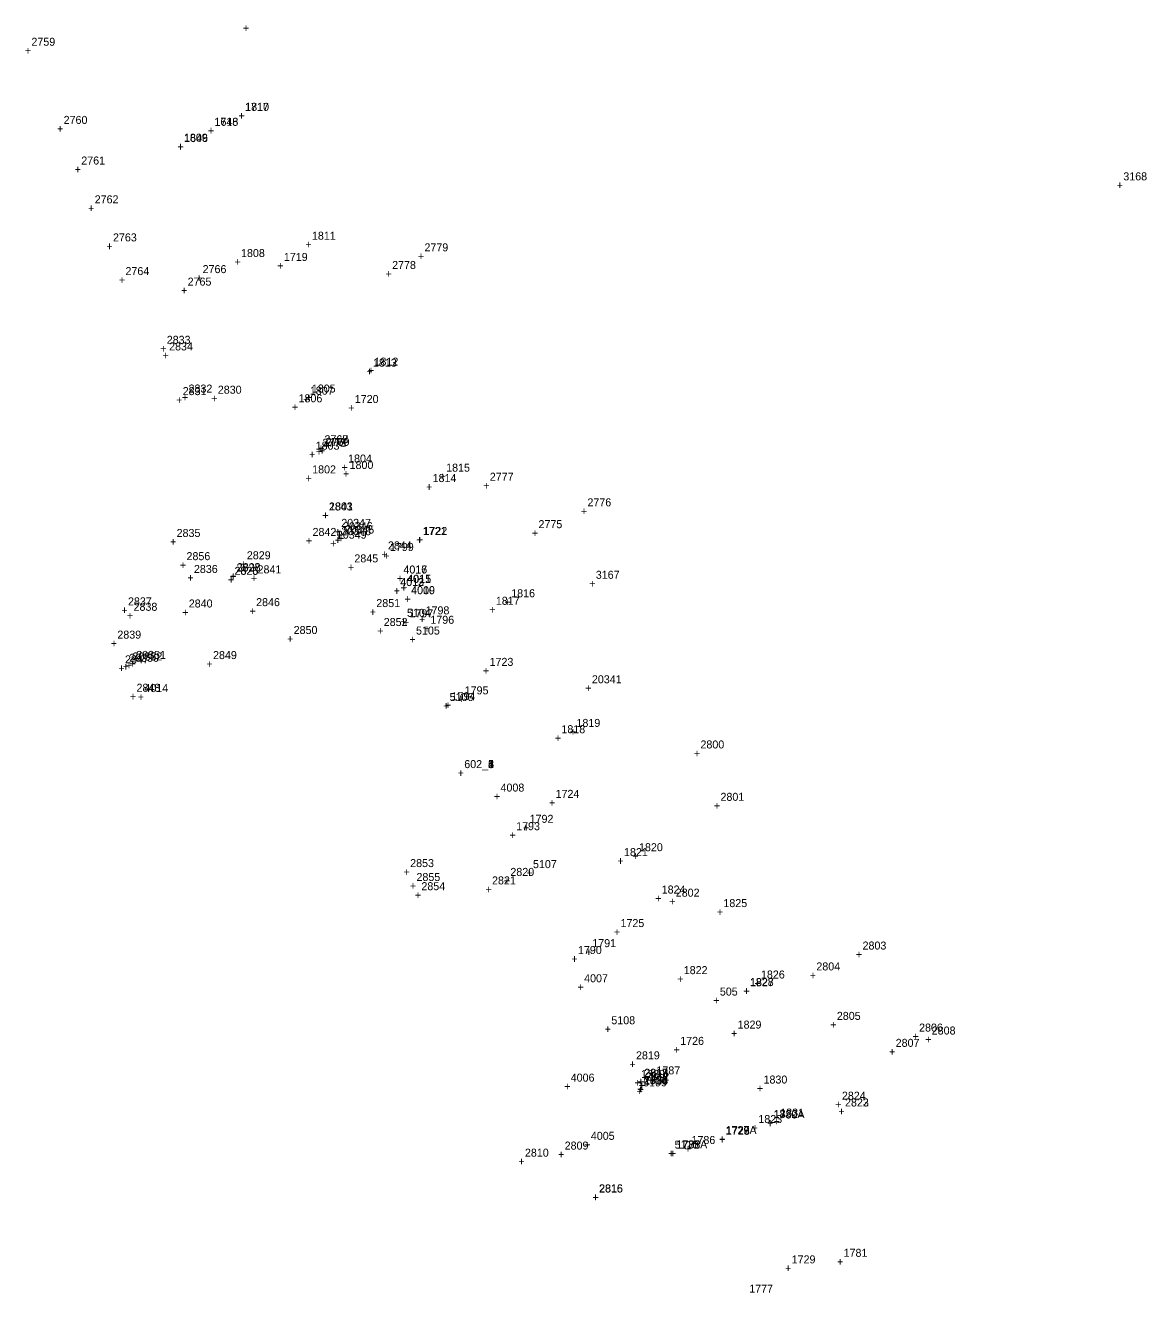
# Model space of a CAD drawing. Extents: x 1036751 to 1042192, y 772604 to 785439.
# Drawn here: x 1039702.1 to 1040052.6, y 775804.7 to 776200.7 of the extents above; entities that cross this region are included whole.
import ezdxf

# ---------------------------------------------------------------- set-up
doc = ezdxf.new("R2010")
doc.units = 0
for name, color, linetype in [('S_Bridge_Centerline', 7, 'Continuous'), ('S_Bridge_Deck', 7, 'Continuous'), ('S_Buildings', 7, 'Continuous'), ('S_Buildings_Attachments', 7, 'Continuous'), ('S_Buildings_SillElevation', 7, 'Continuous'), ('S_Control_Geodetic_ControlPoint', 7, 'Continuous'), ('S_Control_Temp_Traverse', 7, 'Continuous'), ('S_Control_Traverse_Point', 7, 'Continuous'), ('S_Curb_Type_3', 7, 'Continuous'), ('S_Drainage_CB', 7, 'Continuous'), ('S_Drainage_Culvert_Top', 7, 'Continuous'), ('S_Drainage_Invert', 7, 'Continuous'), ('S_Drainage_Sump', 7, 'Continuous'), ('S_Fencing_PostAndRail', 7, 'Continuous'), ('S_Ground_LevelString', 7, 'Continuous'), ('S_Property_IronPipeFound', 7, 'Continuous'), ('S_Property_Mailbox', 7, 'Continuous'), ('S_Roadway_Centerline', 7, 'Continuous'), ('S_Roadway_Edge_Pavement', 7, 'Continuous'), ('S_Roadway_Edge_TW', 7, 'Continuous'), ('S_Traffic_Sign_DoublePost', 7, 'Continuous'), ('S_Traffic_Sign_SinglePost', 7, 'Continuous'), ('S_Trees_Conifer_Pay', 7, 'Continuous'), ('S_Trees_Decid_Pay', 7, 'Continuous'), ('S_Utilities_GuyWire3', 7, 'Continuous'), ('S_Utilities_Pole_Power', 7, 'Continuous'), ('S_Utilities_UG_Sanitary_MH', 7, 'Continuous'), ('S_Utilities_UG_Sanitary_Sewer', 7, 'Continuous'), ('S_Utilities_UG_Water_Gate', 7, 'Continuous'), ('S_Utilities_UG_Water_Line', 7, 'Continuous')]:
    doc.layers.add(name, color=color, linetype=linetype)

msp = doc.modelspace()

# ---------------------------------------------------------------- texts
at = {"layer": 'S_Bridge_Centerline'}
for s, p in [('1728', (1039921.11, 775854.05)), ('+', (1039919.04, 775851.3)), ('+', (1039939.61, 775811.12)), ('1729', (1039941.67, 775813.87))]:
    msp.add_text(s, height=2.5, dxfattribs=at).set_placement(p)
at = {"layer": 'S_Bridge_Deck'}
for s, p in [('1780', (1039936.03, 775859.15)), ('1779', (1039921.04, 775854.1)), ('+', (1039933.97, 775856.4)), ('1778', (1039905.68, 775849.72)), ('+', (1039918.98, 775851.35)), ('+', (1039903.61, 775846.97)), ('1781', (1039957.9, 775815.92)), ('+', (1039955.84, 775813.17)), ('1777', (1039928.4, 775804.72))]:
    msp.add_text(s, height=2.5, dxfattribs=at).set_placement(p)
at = {"layer": 'S_Buildings'}
for s, p in [('2835', (1039749.43, 776040.85)), ('+', (1039747.37, 776038.1)), ('2836', (1039754.84, 776029.6)), ('+', (1039752.78, 776026.85)), ('+', (1039732.17, 776016.72)), ('2837', (1039734.23, 776019.47)), ('2853', (1039822.43, 775937.7)), ('+', (1039820.37, 775934.95)), ('2854', (1039825.94, 775930.48)), ('+', (1039823.88, 775927.73))]:
    msp.add_text(s, height=2.5, dxfattribs=at).set_placement(p)
at = {"layer": 'S_Buildings_Attachments'}
for s, p in [('2833', (1039746.35, 776101.2)), ('+', (1039744.29, 776098.45)), ('2831', (1039751.33, 776085.17)), ('2832', (1039753.16, 776085.97)), ('+', (1039749.27, 776082.42)), ('+', (1039751.1, 776083.22))]:
    msp.add_text(s, height=2.5, dxfattribs=at).set_placement(p)
at = {"layer": 'S_Buildings_SillElevation'}
for s, p in [('2834', (1039747.08, 776099.13)), ('+', (1039745.02, 776096.38)), ('2856', (1039752.52, 776033.6)), ('+', (1039750.46, 776030.85)), ('2855', (1039824.4, 775933.34)), ('+', (1039822.34, 775930.59))]:
    msp.add_text(s, height=2.5, dxfattribs=at).set_placement(p)
at = {"layer": 'S_Control_Geodetic_ControlPoint'}
msp.add_text('+', height=2.5, dxfattribs=at).set_placement((1039770.13, 776198.61))
msp.add_text('+', height=2.5, dxfattribs=at).set_placement((1039770.13, 776198.61))
msp.add_text('+', height=2.5, dxfattribs=at).set_placement((1039770.13, 776198.61))
msp.add_text('+', height=2.5, dxfattribs=at).set_placement((1039770.13, 776198.61))
msp.add_text('+', height=2.5, dxfattribs=at).set_placement((1039770.13, 776198.61))
msp.add_text('+', height=2.5, dxfattribs=at).set_placement((1039770.13, 776198.61))
at = {"layer": 'S_Control_Temp_Traverse'}
for s, p in [('602', (1039839.34, 775968.62)), ('602', (1039839.34, 775968.62)), ('602', (1039839.34, 775968.62)), ('602', (1039839.34, 775968.62)), ('602', (1039839.34, 775968.62)), ('602', (1039839.34, 775968.62)), ('602_6', (1039839.34, 775968.62)), ('602_4', (1039839.34, 775968.62)), ('602_5', (1039839.34, 775968.62)), ('602_2', (1039839.34, 775968.62)), ('602_3', (1039839.34, 775968.62)), ('602_1', (1039839.34, 775968.62)), ('+', (1039837.28, 775965.87)), ('+', (1039837.28, 775965.87)), ('+', (1039837.28, 775965.87)), ('+', (1039837.28, 775965.87)), ('+', (1039837.28, 775965.87)), ('+', (1039837.28, 775965.87)), ('+', (1039837.28, 775965.87)), ('+', (1039837.28, 775965.87)), ('+', (1039837.28, 775965.87)), ('+', (1039837.28, 775965.87)), ('+', (1039837.28, 775965.87)), ('+', (1039837.28, 775965.87))]:
    msp.add_text(s, height=2.5, dxfattribs=at).set_placement(p)
at = {"layer": 'S_Control_Traverse_Point'}
for s, p in [('505', (1039919.22, 775897.55)), ('505', (1039919.22, 775897.55)), ('505', (1039919.22, 775897.55)), ('505', (1039919.22, 775897.55)), ('505', (1039919.22, 775897.55)), ('505', (1039919.22, 775897.55)), ('+', (1039917.16, 775894.8)), ('+', (1039917.16, 775894.8)), ('+', (1039917.16, 775894.8)), ('+', (1039917.16, 775894.8)), ('+', (1039917.16, 775894.8)), ('+', (1039917.16, 775894.8))]:
    msp.add_text(s, height=2.5, dxfattribs=at).set_placement(p)
at = {"layer": 'S_Curb_Type_3'}
for s, p in [('5104', (1039821.43, 776015.9)), ('+', (1039819.37, 776013.15)), ('5105', (1039824.26, 776010.36)), ('+', (1039822.2, 776007.61)), ('5106', (1039834.75, 775989.58)), ('+', (1039832.69, 775986.83)), ('5107', (1039860.82, 775937.37)), ('+', (1039858.76, 775934.62)), ('+', (1039883.25, 775885.84)), ('5108', (1039885.31, 775888.59)), ('+', (1039893.18, 775866.43)), ('5109', (1039895.24, 775869.18)), ('5110', (1039905.09, 775849.73)), ('+', (1039903.03, 775846.98))]:
    msp.add_text(s, height=2.5, dxfattribs=at).set_placement(p)
at = {"layer": 'S_Drainage_CB'}
for s, p in [('2767', (1039795.66, 776070.13)), ('+', (1039793.6, 776067.38)), ('2825', (1039767.5, 776029.02)), ('+', (1039765.44, 776026.27)), ('2811', (1039895.93, 775870.99)), ('+', (1039893.87, 775868.24))]:
    msp.add_text(s, height=2.5, dxfattribs=at).set_placement(p)
at = {"layer": 'S_Drainage_Culvert_Top'}
for s, p in [('2773', (1039795.01, 776069.04)), ('2770', (1039796, 776069.32)), ('+', (1039792.95, 776066.29)), ('+', (1039793.94, 776066.57)), ('2829', (1039771.38, 776033.88)), ('2828', (1039768.23, 776030.16)), ('+', (1039769.32, 776031.13)), ('+', (1039766.17, 776027.41)), ('2819', (1039893.01, 775877.62)), ('+', (1039890.95, 775874.87)), ('2814', (1039895.48, 775869.89)), ('2818', (1039895.65, 775872.12)), ('+', (1039893.42, 775867.14)), ('+', (1039893.58, 775869.37)), ('+', (1039955.31, 775862.27)), ('2824', (1039957.37, 775865.02)), ('2823', (1039958.35, 775862.91)), ('+', (1039956.28, 775860.16)), ('2815', (1039881.51, 775836.01)), ('+', (1039879.44, 775833.26))]:
    msp.add_text(s, height=2.5, dxfattribs=at).set_placement(p)
at = {"layer": 'S_Drainage_Invert'}
for s, p in [('2772', (1039795, 776069.06)), ('2769', (1039796.02, 776069.32)), ('+', (1039792.94, 776066.31)), ('+', (1039793.96, 776066.57)), ('2827', (1039768.15, 776030.03)), ('+', (1039766.09, 776027.28)), ('2813', (1039895.44, 775869.86)), ('2817', (1039895.58, 775872.19)), ('+', (1039893.38, 775867.11)), ('+', (1039893.52, 775869.44)), ('2822', (1039958.34, 775862.9)), ('+', (1039956.28, 775860.15)), ('2816', (1039881.45, 775836.07)), ('+', (1039879.39, 775833.32))]:
    msp.add_text(s, height=2.5, dxfattribs=at).set_placement(p)
at = {"layer": 'S_Drainage_Sump'}
for s, p in [('2768', (1039795.64, 776070.12)), ('+', (1039793.58, 776067.37)), ('2826', (1039767.56, 776029.02)), ('+', (1039765.5, 776026.27)), ('2812', (1039895.97, 775871.04)), ('+', (1039893.91, 775868.29))]:
    msp.add_text(s, height=2.5, dxfattribs=at).set_placement(p)
at = {"layer": 'S_Fencing_PostAndRail'}
for s, p in [('2803', (1039963.83, 775911.93)), ('2804', (1039949.39, 775905.41)), ('+', (1039961.77, 775909.18)), ('+', (1039947.33, 775902.66)), ('2805', (1039955.79, 775889.95)), ('+', (1039953.73, 775887.2)), ('2806', (1039981.49, 775886.3)), ('+', (1039979.43, 775883.55))]:
    msp.add_text(s, height=2.5, dxfattribs=at).set_placement(p)
at = {"layer": 'S_Ground_LevelString'}
for s, p in [('1800', (1039803.49, 776062.1)), ('+', (1039801.43, 776059.35)), ('1799', (1039816.1, 776036.46)), ('+', (1039814.04, 776033.71)), ('1798', (1039827.25, 776016.66)), ('+', (1039825.19, 776013.91)), ('1832A', (1039936.03, 775859.29)), ('1727A', (1039921.04, 775854.25)), ('+', (1039933.97, 775856.54)), ('1785A', (1039905.62, 775849.79)), ('+', (1039918.98, 775851.5)), ('+', (1039903.56, 775847.04))]:
    msp.add_text(s, height=2.5, dxfattribs=at).set_placement(p)
at = {"layer": 'S_Property_IronPipeFound'}
for s, p in [('3168', (1040045.33, 776152.27)), ('+', (1040043.27, 776149.52)), ('3167', (1039880.45, 776027.78)), ('+', (1039878.39, 776025.03))]:
    msp.add_text(s, height=2.5, dxfattribs=at).set_placement(p)
at = {"layer": 'S_Property_Mailbox'}
for s, p in [('+', (1039903.38, 775925.7)), ('2802', (1039905.44, 775928.45))]:
    msp.add_text(s, height=2.5, dxfattribs=at).set_placement(p)
at = {"layer": 'S_Roadway_Centerline'}
for s, p in [('1718', (1039761.26, 776169.34)), ('1645', (1039761.28, 776169.3)), ('+', (1039759.2, 776166.59)), ('+', (1039759.22, 776166.55)), ('1719', (1039782.95, 776127.09)), ('+', (1039780.89, 776124.34)), ('+', (1039803.06, 776079.95)), ('1720', (1039805.12, 776082.7)), ('1721', (1039826.36, 776041.44)), ('1722', (1039826.57, 776041.48)), ('2844', (1039815.48, 776036.96)), ('+', (1039824.3, 776038.69)), ('+', (1039824.5, 776038.73)), ('2845', (1039804.99, 776032.9)), ('+', (1039813.41, 776034.21)), ('+', (1039802.93, 776030.15)), ('+', (1039772.22, 776016.48)), ('2846', (1039774.28, 776019.23)), ('2847', (1039733.3, 776001.36)), ('1723', (1039847.24, 776000.57)), ('+', (1039731.24, 775998.61)), ('+', (1039845.18, 775997.82)), ('1724', (1039867.88, 775959.33)), ('+', (1039865.82, 775956.58)), ('1725', (1039888.17, 775918.95)), ('+', (1039886.11, 775916.2)), ('1726', (1039906.83, 775882.15)), ('+', (1039904.77, 775879.4)), ('1727', (1039921.04, 775854.25)), ('+', (1039918.98, 775851.5))]:
    msp.add_text(s, height=2.5, dxfattribs=at).set_placement(p)
at = {"layer": 'S_Roadway_Edge_Pavement'}
for s, p in [('+', (1039768.72, 776171.23)), ('+', (1039768.82, 776171.25)), ('1717', (1039770.78, 776173.98)), ('1810', (1039770.88, 776174)), ('1809', (1039751.72, 776164.36)), ('1646', (1039751.78, 776164.24)), ('+', (1039749.66, 776161.61)), ('+', (1039749.72, 776161.49)), ('1811', (1039791.73, 776133.73)), ('1808', (1039769.57, 776128.31)), ('+', (1039789.66, 776130.98)), ('+', (1039767.51, 776125.56)), ('+', (1039809.23, 776091.64)), ('1812', (1039811.29, 776094.39)), ('1807', (1039791.07, 776085.3)), ('+', (1039785.48, 776080.18)), ('1806', (1039787.54, 776082.93)), ('+', (1039789.01, 776082.55)), ('1803', (1039792.89, 776068.12)), ('+', (1039790.83, 776065.37)), ('1802', (1039791.8, 776060.71)), ('1815', (1039833.68, 776061.25)), ('+', (1039789.74, 776057.96)), ('+', (1039831.62, 776058.5)), ('2843', (1039797.01, 776049.12)), ('1801', (1039797.11, 776049.16)), ('+', (1039794.95, 776046.37)), ('+', (1039795.05, 776046.41)), ('2842', (1039791.92, 776041.17)), ('+', (1039789.86, 776038.42)), ('2841', (1039774.73, 776029.47)), ('+', (1039772.67, 776026.72)), ('1816', (1039854.01, 776022.01)), ('2840', (1039753.23, 776018.81)), ('2851', (1039811.85, 776018.94)), ('+', (1039851.94, 776019.26)), ('+', (1039751.17, 776016.06)), ('+', (1039809.79, 776016.19)), ('+', (1039820.16, 776012.99)), ('1797', (1039822.22, 776015.74)), ('2839', (1039730.91, 776009.08)), ('2850', (1039786.01, 776010.52)), ('+', (1039728.85, 776006.33)), ('+', (1039783.95, 776007.77)), ('2849', (1039760.81, 776002.69)), ('+', (1039758.75, 775999.94)), ('2848', (1039736.9, 775992.49)), ('+', (1039734.84, 775989.74)), ('1794', (1039835.35, 775989.84)), ('+', (1039833.29, 775987.09)), ('1819', (1039874.41, 775981.5)), ('+', (1039872.35, 775978.75)), ('1793', (1039855.56, 775949.23)), ('+', (1039853.5, 775946.48)), ('1820', (1039893.96, 775942.66)), ('+', (1039891.9, 775939.91)), ('1824', (1039901.05, 775929.44)), ('+', (1039898.99, 775926.69)), ('1825', (1039920.33, 775925.2)), ('+', (1039918.27, 775922.45)), ('1790', (1039874.87, 775910.52)), ('+', (1039872.81, 775907.77)), ('1826', (1039932.07, 775902.88)), ('+', (1039926.54, 775897.79)), ('+', (1039926.61, 775897.71)), ('1828', (1039928.6, 775900.54)), ('1827', (1039928.68, 775900.46)), ('+', (1039930.01, 775900.13)), ('1829', (1039924.78, 775887.23)), ('+', (1039922.72, 775884.48)), ('1789', (1039894.62, 775871.83)), ('1788', (1039895.61, 775869.75)), ('1830', (1039932.88, 775870.06)), ('+', (1039892.56, 775869.08)), ('+', (1039893.55, 775867)), ('+', (1039930.82, 775867.31)), ('1832', (1039936.03, 775859.29)), ('1831', (1039938.1, 775859.74)), ('+', (1039933.97, 775856.54)), ('+', (1039936.04, 775856.99)), ('1785', (1039905.62, 775849.79)), ('+', (1039903.56, 775847.04))]:
    msp.add_text(s, height=2.5, dxfattribs=at).set_placement(p)
at = {"layer": 'S_Roadway_Edge_TW'}
for s, p in [('1813', (1039810.79, 776094.05)), ('+', (1039808.73, 776091.3)), ('1805', (1039791.69, 776085.98)), ('+', (1039789.62, 776083.23)), ('1804', (1039803.03, 776064.11)), ('+', (1039800.97, 776061.36)), ('1814', (1039829.44, 776058)), ('+', (1039827.38, 776055.25)), ('+', (1039847.14, 776016.9)), ('1817', (1039849.2, 776019.65)), ('1796', (1039828.74, 776013.72)), ('+', (1039826.68, 776010.97)), ('+', (1039837.41, 775988.92)), ('1795', (1039839.47, 775991.67)), ('+', (1039867.64, 775976.78)), ('1818', (1039869.7, 775979.53)), ('1792', (1039859.77, 775951.53)), ('+', (1039857.71, 775948.78)), ('1821', (1039889.27, 775941.14)), ('+', (1039887.2, 775938.39)), ('+', (1039877.29, 775909.94)), ('1791', (1039879.35, 775912.69)), ('+', (1039905.88, 775901.5)), ('1822', (1039907.94, 775904.25)), ('+', (1039897.34, 775870.17)), ('1787', (1039899.4, 775872.92)), ('1823', (1039931.26, 775857.73)), ('+', (1039929.2, 775854.98)), ('1786', (1039910.36, 775851.17)), ('+', (1039908.29, 775848.42))]:
    msp.add_text(s, height=2.5, dxfattribs=at).set_placement(p)
at = {"layer": 'S_Traffic_Sign_DoublePost'}
for s, p in [('2820', (1039853.75, 775934.94)), ('+', (1039845.96, 775929.53)), ('2821', (1039848.02, 775932.28)), ('+', (1039851.69, 775932.19))]:
    msp.add_text(s, height=2.5, dxfattribs=at).set_placement(p)
at = {"layer": 'S_Traffic_Sign_SinglePost'}
for s, p in [('2766', (1039757.56, 776123.29)), ('+', (1039755.5, 776120.54)), ('2777', (1039847.32, 776058.41)), ('+', (1039845.25, 776055.66)), ('2838', (1039735.97, 776017.78)), ('+', (1039733.91, 776015.03)), ('2852', (1039814.17, 776013.03)), ('+', (1039812.11, 776010.28)), ('20341', (1039879.23, 775995.13)), ('+', (1039877.17, 775992.38))]:
    msp.add_text(s, height=2.5, dxfattribs=at).set_placement(p)
at = {"layer": 'S_Trees_Conifer_Pay'}
for s, p in [('2759', (1039704.05, 776194.33)), ('+', (1039701.98, 776191.58)), ('+', (1039712.06, 776167.16)), ('2760', (1039714.12, 776169.91)), ('2761', (1039719.63, 776157.22)), ('+', (1039717.57, 776154.47)), ('2762', (1039723.82, 776145.09)), ('+', (1039721.76, 776142.34)), ('2763', (1039729.54, 776133.2)), ('+', (1039727.48, 776130.45)), ('+', (1039731.38, 776119.92)), ('2764', (1039733.44, 776122.67)), ('2800', (1039913.16, 775974.77)), ('+', (1039911.1, 775972.02)), ('2801', (1039919.42, 775958.4)), ('+', (1039917.36, 775955.65))]:
    msp.add_text(s, height=2.5, dxfattribs=at).set_placement(p)
at = {"layer": 'S_Trees_Decid_Pay'}
for s, p in [('+', (1039824.84, 776127.34)), ('2779', (1039826.9, 776130.09)), ('2830', (1039762.31, 776085.61)), ('+', (1039760.25, 776082.86))]:
    msp.add_text(s, height=2.5, dxfattribs=at).set_placement(p)
at = {"layer": 'S_Utilities_GuyWire3'}
for s, p in [('2776', (1039877.84, 776050.42)), ('+', (1039875.78, 776047.67)), ('2808', (1039985.45, 775885.38)), ('+', (1039983.39, 775882.63)), ('2810', (1039858.3, 775847.21)), ('+', (1039856.24, 775844.46))]:
    msp.add_text(s, height=2.5, dxfattribs=at).set_placement(p)
at = {"layer": 'S_Utilities_Pole_Power'}
for s, p in [('2778', (1039816.79, 776124.57)), ('2765', (1039752.87, 776119.38)), ('+', (1039814.73, 776121.82)), ('+', (1039750.81, 776116.63)), ('2775', (1039862.54, 776043.6)), ('+', (1039860.48, 776040.85)), ('2807', (1039974.18, 775881.53)), ('+', (1039972.12, 775878.78)), ('+', (1039868.66, 775846.68)), ('2809', (1039870.72, 775849.43))]:
    msp.add_text(s, height=2.5, dxfattribs=at).set_placement(p)
at = {"layer": 'S_Utilities_UG_Sanitary_MH'}
for s, p in [('20345', (1039801.89, 776041.9)), ('+', (1039799.83, 776039.15)), ('20350', (1039734.63, 776001.85)), ('+', (1039732.57, 775999.1))]:
    msp.add_text(s, height=2.5, dxfattribs=at).set_placement(p)
at = {"layer": 'S_Utilities_UG_Sanitary_Sewer'}
for s, p in [('20347', (1039800.89, 776044)), ('+', (1039798.83, 776041.25)), ('+', (1039799.38, 776040.21)), ('20349', (1039799.51, 776040.32)), ('20348', (1039800.91, 776041.41)), ('20346', (1039801.44, 776042.96)), ('+', (1039797.45, 776037.57)), ('+', (1039798.85, 776038.66)), ('20352', (1039735.65, 776002.26)), ('20351', (1039736.79, 776002.74)), ('+', (1039733.59, 775999.51)), ('+', (1039734.73, 775999.99))]:
    msp.add_text(s, height=2.5, dxfattribs=at).set_placement(p)
at = {"layer": 'S_Utilities_UG_Water_Gate'}
for s, p in [('4017', (1039820.33, 776029.41)), ('+', (1039818.27, 776026.66)), ('4013', (1039819.33, 776025.56)), ('+', (1039817.27, 776022.81)), ('+', (1039820.66, 776020.26)), ('4010', (1039822.72, 776023.01))]:
    msp.add_text(s, height=2.5, dxfattribs=at).set_placement(p)
at = {"layer": 'S_Utilities_UG_Water_Line'}
for s, p in [('4016', (1039820.31, 776029.44)), ('+', (1039818.25, 776026.69)), ('4012', (1039819.35, 776025.49)), ('4011', (1039821.45, 776026.51)), ('4015', (1039821.56, 776026.54)), ('+', (1039817.29, 776022.74)), ('+', (1039819.39, 776023.76)), ('+', (1039819.5, 776023.79)), ('4009', (1039822.74, 776022.95)), ('+', (1039820.68, 776020.2)), ('4014', (1039739.35, 775992.38)), ('+', (1039737.29, 775989.63)), ('4008', (1039850.67, 775961.29)), ('+', (1039848.61, 775958.54)), ('4007', (1039876.8, 775901.71)), ('+', (1039874.74, 775898.96)), ('4006', (1039872.61, 775870.66)), ('+', (1039870.55, 775867.91)), ('4005', (1039878.9, 775852.48)), ('+', (1039876.84, 775849.73))]:
    msp.add_text(s, height=2.5, dxfattribs=at).set_placement(p)

doc.saveas('drawing.dxf')
